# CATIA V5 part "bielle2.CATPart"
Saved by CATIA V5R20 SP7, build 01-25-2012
Part number: bielle2
Bounding box of the stored display mesh (mm): x 0 to 30, y -90 to 117.223, z -10 to 40.291
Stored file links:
  F:\IAO_Mecanisme_991\IAO_Mecanisme_991_CATIA\Assemblage\bielle2.CATPart
  F:\IAO_Mecanisme_991\IAO_Mecanisme_991_CATIA\Assemblage\Ass_IAO_991_skl.CATProduct
  F:\IAO_Mecanisme_991\IAO_Mecanisme_991_CATIA\skl_bielle_2.CATPart
  F:\IAO_Mecanisme_991\IAO_Mecanisme_991_CATIA\skl_rainure_circulaire.CATPart
  F:\IAO_Mecanisme_991\IAO_Mecanisme_991_CATIA\Assemblage\bati.CATPart
  F:\IAO_Mecanisme_991\IAO_Mecanisme_991_CATIA\Assemblage\rainure_circulaire.CATPart
  F:\IAO_Mecanisme_991\IAO_Mecanisme_991_CATIA\skl_bati.CATPart
  F:\IAO_Mecanisme_991\IAO_Mecanisme_991_CATIA\Assemblage\excentrique.CATPart
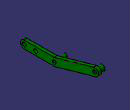
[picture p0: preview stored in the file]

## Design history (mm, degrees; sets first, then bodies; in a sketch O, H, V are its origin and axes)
Set1
  Plane1 "plan_ref_yz": linked copy from another document
  DatumSurface1: linked copy from another document
  Line1: linked copy from another document
  Line2: linked copy from another document
  DatumPoint1: linked copy from another document
  Point1: linked copy from another document
  Line3: linked copy from another document
  DatumPoint2: linked copy from another document
  DatumPoint3: linked copy from another document
  DatumSurface2: linked copy from another document
  DatumCurve1: linked copy from another document
  DatumCurve2: linked copy from another document
Body1 (main body)
  Plane2: type Offset, RefPlane DatumSurface1, Offset 2, reversed
  Sketch1 on Plane2, origin (22, 0, 0), H (0, -1, 0), V (0, 0, 1)
    arc A1 centre (80, 0) radius 10 from (80, -10) to (80.049, 9.9999) ccw
    point P3 (80, 0)
    reference projected point E1 (80, 0) from vertex of DatumPoint1
    line L1 (80, -10) -> (-1.3864, -10)
    point P5 (-1.3864, -10)
    line L2 (-1.3864, -10) -> (-109.9748, 20.6992)
    point P6 (-1.3864, -10)
    point P7 (-109.9748, 20.6992)
    arc A2 centre (-107.2543, 30.322) radius 10 from (-104.5338, 39.9449) to (-109.9748, 20.6992) ccw
    point P8 (-107.2543, 30.322)
    point P9 (-109.9748, 20.6992)
    reference projected point E2 (-107.2543, 30.322) from Point1
    line L3 (80.049, 9.9999) -> (0, 10.3919)
    point P10 (0, 10.3919)
    line L4 (0, 10.3919) -> (-104.5338, 39.9449)
    point P11 (0, 10.3919)
    reference projected line E3 (-107.2543, 30.322) -> (0, 0) from Line1
    reference projected line E4 (-107.2543, 30.322) -> (0, 0) from Line1
    circle A3 centre (80, 0) radius 5
    point P12 (80, 0)
    reference projected point E5 (80, 0) from DatumPoint1
    point P13 (0, 0)
    circle A4 centre (0, 0) radius 5
    reference projected point E6 (0, 0) from vertex of DatumPoint2
    point P14 (-107.2543, 30.322)
    circle A5 centre (-107.2543, 30.322) radius 5
    circle A6 centre (50, 0) radius 5
    point P15 (50, 0)
    reference projected point E7 (50, 0) from vertex of DatumPoint3
    radius A2 = 10
    radius A1 = 10
    radius A4 = 5
    radius A3 = 5
    radius A5 = 5
    radius A6 = 5
    coincidence: P3 E1, P9 L2, P9 P7, P8 E2, P10 V, P11 L3, P11 P10, P6 P5, E5 P12, E6 P13, P8 P14, E7 P15
    tangency: L1 A1, L2 A2, L3 A1, L4 A2
    horizontal: L1 H
    parallelism: L4 E3
    symmetry: L2 L4 E4
  Pad1: profile Sketch1, direction (1, 0, 0), length 8
  Sketch2 on start face of Pad1, origin (22, 0, 0), H (0, -1, 0), V (0, 0, 1)
    circle A1 centre (-107.2543, 30.322) radius 5
    point P1 (-107.2543, 30.322)
    reference projected point E1 (-107.2543, 30.322) from Point1
    reference projected circle E2 centre (-107.2543, 30.322) radius 5 from edge [start face of Pad1 | face of Pad1 from Sketch1.A5]
    coincidence: P1 E1, A1 E2
  Pad2: profile Sketch2, direction (-1, 0, 0), length 12, opposite side length 5
  Sketch3 on start face of Pad1, origin (22, 0, 0), H (0, -1, 0), V (0, 0, 1)
    circle A1 centre (0, 0) radius 5
    reference projected circle E1 centre (0, 0) radius 5 from edge [start face of Pad1 | face of Pad1 from Sketch1.A4]
    coincidence: A1 E1
  Pad3: profile Sketch3, direction (-1, 0, 0), up to DatumSurface2, opposite side length 5
  Sketch4 on end face of Pad2, origin (10, 0, 0), H (0, -1, 0), V (0, 0, 1)
    circle A1 centre (-107.2543, 30.322) radius 7.7913
    point P1 (-107.2543, 30.322)
    reference projected point E1 (-107.2543, 30.322) from Point1
    reference projected curve E2 from edge of DatumCurve2
    distance A1 E2 = 0
    coincidence: P1 E1
  Pad4: profile Sketch4, direction (1, 0, 0), length 10
  Plane3: type Offset, RefPlane DatumSurface1, Offset 0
